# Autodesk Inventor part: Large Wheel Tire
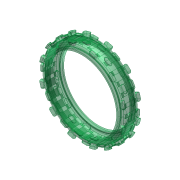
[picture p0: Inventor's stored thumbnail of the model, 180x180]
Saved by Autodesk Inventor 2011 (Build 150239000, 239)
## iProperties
Created: 2010-06
Part Number: Large Wheel Tire
Document SubType Name: Modeling
Designer: kurdi
Density: 1 g/cm^3
Author: kurdi
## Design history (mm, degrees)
sketch "Sketch2"
  geometry: L1 (-50.934, -12.364)-(-53.055, -12.587); L2 (-50.798, -7.364)-(-50.798, -12.213); L3 (-53.062, -7.445)-(-51.162, -7.065); L4 (-53.307, -8.998)-(-53.307, -7.744); L5 (-56.063, -9.506)-(-53.815, -9.506); L6 (-59.993, 5.714)-(-59.993, -5.714); L7 (-53.815, 9.506)-(-56.063, 9.506); L8 (-53.307, 7.744)-(-53.307, 8.998); L9 (-51.162, 7.065)-(-53.062, 7.445); L10 (-50.798, 12.213)-(-50.798, 7.364); L11 (-53.055, 12.587)-(-50.934, 12.364); L12 (-50.956, 12.614)-(-56.619, 12.606); L13 (-56.223, -12.609)-(-51.352, -12.611); L14 (0.002, 0)-(0.002, 20.428); L15 (0.002, 0)-(-63.498, 0); A1 r 5 centre (-53.577, -7.614) between (-54.516, -12.525) and (-53.055, -12.587); A2 r 0.152 centre (-50.95, -12.213) between (-50.934, -12.364) and (-50.798, -12.213); A3 r 0.305 centre (-51.103, -7.364) between (-50.798, -7.364) and (-51.162, -7.065); A4 r 0.305 centre (-53.003, -7.744) between (-53.062, -7.445) and (-53.307, -7.744); A5 r 0.508 centre (-53.815, -8.998) between (-53.815, -9.506) and (-53.307, -8.998); A6 r 0.508 centre (-53.815, 8.998) between (-53.307, 8.998) and (-53.815, 9.506); A7 r 0.305 centre (-53.003, 7.744) between (-53.307, 7.744) and (-53.062, 7.445); A8 r 0.305 centre (-51.103, 7.364) between (-51.162, 7.065) and (-50.798, 7.364); A9 r 0.152 centre (-50.95, 12.213) between (-50.798, 12.213) and (-50.934, 12.364); A10 r 5 centre (-53.577, 7.614) between (-53.055, 12.587) and (-54.516, 12.525); A11 r 4.051 centre (-53.782, 8.559) between (-51.81, 12.098) and (-55.764, 12.092); A12 r 2.805 centre (-53.786, -9.805) between (-55.388, -12.108) and (-52.187, -12.109); 12 further points
  constraints: 30 end point, 24 point on circle, 12 centre point, 4 midpoint, 1 collinear, 1 parallel, 1 perpendicular, 22 other
  dimensions: "d0" = 0.1524 radius of A2; "d1" = 0.3048 radius of A3; "d2" = 0.3048 radius of A4; "d3" = 0.508 radius of A5; "d4" = 0.1524 radius of A9; "d5" = 0.3048 radius of A8; "d6" = 0.3048 radius of A7; "d7" = 0.508 radius of A6; "d8" = 63.5 distance of L14.start L15.end; "d9" = 4.849 distance of L10.start L10.end; "d10" = 4.849 distance of L2.start L2.end; "d11" = 9.1948 distance between parallel lines of L6 L10; "d12" = 50.8 distance between parallel lines of L14 L10; "d13" = 20.4284 distance of L14.start L14.end; "d73" = 9.50561 distance from line of L5.start L15
revolve "Revolution1" sketch "Sketch2" stored, may be unused: angle "d14" = 90 deg
sketch "Sketch3"
  geometry: L1 (-64.75, 8.409)-(-61.304, 7.155); L2 (-64.75, 3.456)-(-64.75, 8.409); L3 (-61.304, 2.848)-(-64.75, 3.456); L4 (-59.993, 5.714)-(-59.993, -5.714) reference; L5 (-61.304, 7.155)-(-61.304, 2.848); L6 (0, -8.538)-(0, 11.234) reference; 2 further points
  constraints: 8 end point, 1 parallel, 1 vertical
  dimensions: "d19" = 61.30415 distance from line of point (0, 0) L5; "d20" = 2.84832 vertical distance of L3.start point (0, 0); "d21" = 4.30647 distance of L1.end L3.start; "d25" = 110 deg angle of L5 L1; "d27" = 80 deg angle of L5 L3; "d29" = 59.99265 distance from line of point (0, 0) L4; "d33" = 64.75 distance from line of L6 L1.start
revolve "Revolution2" sketch "Sketch3" stored, may be unused: angle "d32" = 9.9236 deg
fillet "Fillet1" dims "d35" = 2.4765
fillet "Fillet2" dims "d36" = 2.4765
fillet "Fillet3" dims "d37" = 0.3048
workplane "Work Plane1"
sketch "Sketch4"
  geometry: L1 (13.558, 62.164)-(11.67, 55.998); L2 (8.605, 62.074)-(13.558, 62.164); L3 (7.589, 60.941)-(8.605, 62.074); L4 (2.477, 64.715)-(2.477, 62.581); L5 (-2.477, 64.715)-(2.477, 64.715); L6 (-2.477, 62.581)-(-2.477, 64.715); L7 (11.67, 55.998)-(7.589, 60.941); L8 (2.477, 62.581)-(-2.477, 62.581); L9 (-5.683, 0)-(16.765, 0) reference; 2 further points
  constraints: 16 end point, 2 vertical, 1 horizontal, 1 midpoint, 1 perpendicular, 1 vertical alignment
  dimensions: "d39" = 64.71499 distance between parallel lines of L9 L5; "d40" = 62.16413 distance from line of L9 L1.start; "d41" = 62.07385 distance from line of L9 L2.start; "d42" = 62.58088 distance between parallel lines of L9 L8; "d43" = 4.953 distance of L5.start L4.start; "d46" = 1.016 horizontal distance of L3.start L2.start; "d47" = 1.13328 vertical distance of L3.start L2.start; "d49" = 7.58944 horizontal distance of point (0, 0) L3.start; "d52" = 4.953 horizontal distance of L2.start L1.start; "d53" = 6.16648 vertical distance of L1.start L1.end; "d54" = 1.88801 horizontal distance of L1.start L1.end
revolve "Revolution3" stored, may be unused: angle "d50" = 9.9236 deg
fillet "Fillet5" dims "d55" = 2.032
fillet "Fillet6" dims "d56" = 0.3048
revolve "Revolution4" stored, may be unused: angle "d58" = 9.9236 deg
fillet "Fillet8" dims "d59" = 2.4765
fillet "Fillet9" dims "d60" = 0.3048
mirror "Mirror1"
sketch "Sketch5"
  geometry: L1 (0, 0)-(71.999, 0); L2 (59.951, 2.286)-(59.438, 2.414); L3 (59.951, -2.286)-(59.438, -2.414); L4 (58.166, 14.701)-(57.637, 14.719); L5 (59.116, 10.229)-(58.641, 9.997); A1 r 59.995 centre (0, 0) between (59.951, 2.286) and (59.951, -2.286); A2 r 59.995 centre (0, 0) between (59.951, -2.286) and (59.951, 2.286); A3 r 59.995 centre (0, 0) between (59.116, 10.229) and (58.166, 14.701); A4 r 59.487 centre (0, 0) between (59.438, -2.414) and (59.438, 2.414); A5 r 59.487 centre (0, 0) between (58.641, 9.997) and (57.637, 14.719); A6 r 59.995 centre (0, 0) between (59.951, 2.286) and (59.116, 10.229); A7 r 59.487 centre (0, 0) between (59.438, 2.414) and (58.641, 9.997); 3 further points
  constraints: 15 point on circle, 10 end point, 7 centre point, 3 concentric, 2 coincident, 1 horizontal, 1 point on line, 10 other
  dimensions: "d64" = 119.9896 diameter of A1; "d65" = 4.572 distance of L3.start L2.start; "d66" = 14 deg angle of L1 L2; "d67" = 14 deg angle of L1 L3; "d71" = 12 deg dimension on point (0, 0) L3.start L5.start; "d76" = 0.508 radial gap between concentric circles of A6 A7
extrude "Extrusion1" join sketch "Sketch5" stored distance "d74" = 19.304; taper "d75" = 0 deg
sketch "Sketch6"
  geometry: L1 (0, 0)-(59.995, 0); L2 (59.951, 2.286)-(56.916, 3.043); L3 (59.951, -2.286)-(56.916, -3.043); A1 r 59.995 centre (0, 0) between (59.995, 0) and (59.951, 2.286); A2 r 56.998 centre (0, 0) between (56.916, 3.043) and (56.916, -3.043); A3 r 59.995 centre (0, 0) between (59.951, -2.286) and (59.951, 2.286); A4 r 56.998 centre (0, 0) between (56.916, -3.043) and (56.916, 3.043); 2 further points
  constraints: 10 point on circle, 6 end point, 4 centre point, 2 coincident, 2 concentric, 1 horizontal, 1 point on line
  dimensions: "d78" = 119.9896 diameter of A1; "d79" = 113.9952 diameter of A2; "d80" = 4.572 distance of L3.start L2.start; "d81" = 14 deg angle of L1 L2; "d82" = 14 deg angle of L1 L3
extrude "Extrusion2" cut sketch "Sketch6" stored distance "d83" = 16.9926; taper "d84" = 0 deg
sketch "Sketch7"
  geometry: L1 (-59.951, 8.496)-(-59.951, -8.496) reference; L2 (-59.951, 8.496)-(-57.79, 8.496) reference; L3 (-59.951, 8.496)-(-57.843, 8.496); L4 (-59.951, 0)-(-59.951, 5.715); L5 (-59.951, 5.715)-(-59.951, 8.496); L6 (0, -18.986)-(0, 18.986) reference; A1 r 3.81 centre (-56.198, 5.06) between (-57.843, 8.496) and (-59.951, 5.715); 2 further points
  constraints: 6 end point, 3 collinear, 2 coincident, 2 point on circle, 1 centre point, 1 midpoint, 1 perpendicular
  dimensions: "d85" = 2.1082 distance of L3.start L3.end; "d87" = 5.715 distance of L4.start L4.end; "d88" = 3.81 radius of A1
revolve "Revolution5" stored, may be unused: angle "d92" = 9.9236 deg
mirror "Mirror2"
body "Solid1"
pattern_circular "Circular Pattern1" dims "d62" = 360 deg
pattern_circular "Circular Pattern2" dims angle "d90" = 360 deg
other parameters: "d38" = 15 deg, "d68" = 0.762
